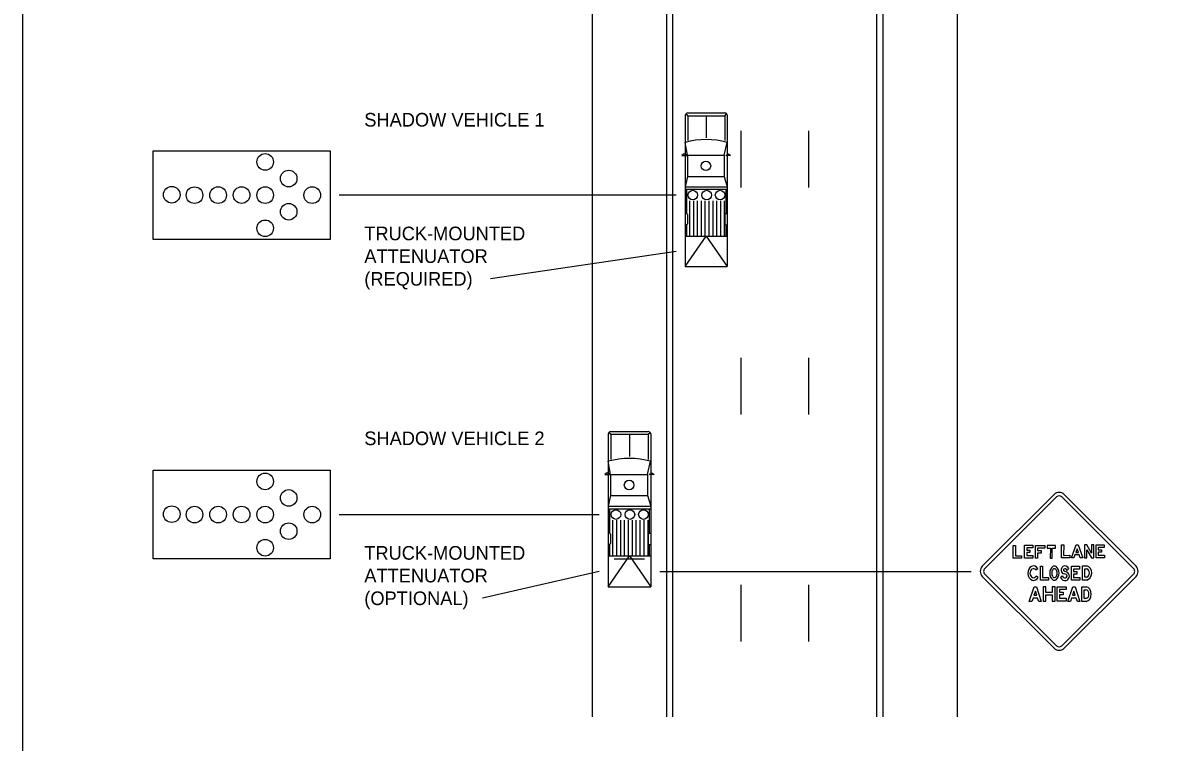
# Model space of a CAD drawing. Extents: x 49991.4 to 50021, y 49987.6 to 50011.4.
# Drawn here: x 49999.38 to 50004.39, y 49992.66 to 49995.83 of the extents above; entities that cross this region are included whole.
import ezdxf

# ---------------------------------------------------------------- set-up
doc = ezdxf.new("R2010")
doc.units = 0
for name, color, linetype in [('Level 1', 7, 'Continuous'), ('Level 2', 7, 'Continuous'), ('Level 3', 7, 'Continuous')]:
    doc.layers.add(name, color=color, linetype=linetype)

msp = doc.modelspace()

# ---------------------------------------------------------------- linework, layer by layer
at = {"layer": 'Level 1'}
for p, q in [((50001.8915, 49992.7699), (50001.8915, 49997.7045)), ((50002.2188, 49992.7699), (50002.2188, 49997.7045)), ((50002.2461, 49992.7699), (50002.2461, 49997.7045)), ((50003.1448, 49992.7699), (50003.1448, 49997.7045)), ((50003.172, 49992.7699), (50003.172, 49997.7045)), ((50003.4993, 49992.7699), (50003.4993, 49997.7045)), ((50002.3118, 49995.431), (50002.475, 49995.431)), ((50002.3002, 49995.4193), (50002.3002, 49994.754)), ((50002.3118, 49995.4189), (50002.3044, 49995.428)), ((50002.3118, 49995.4189), (50002.475, 49995.4189)), ((50002.3118, 49995.4189), (50002.3118, 49995.3096)), ((50002.3934, 49995.4189), (50002.3934, 49995.3217)), ((50002.475, 49995.4189), (50002.4827, 49995.4274)), ((50002.475, 49995.4189), (50002.475, 49995.3096)), ((50002.4854, 49995.4211), (50002.4854, 49994.7541)), ((50002.5461, 49995.1021), (50002.5461, 49995.352)), ((50002.8448, 49995.1021), (50002.8448, 49995.352)), ((50002.3104, 49995.2442), (50002.3001, 49995.3012)), ((50002.4721, 49995.2442), (50002.485, 49995.3012)), ((50002.3104, 49995.2442), (50002.4721, 49995.2442)), ((50002.3104, 49995.2439), (50002.3104, 49995.1518)), ((50002.4721, 49995.2439), (50002.4721, 49995.1518)), ((50002.3104, 49995.1515), (50002.3002, 49995.1052)), ((50002.3104, 49995.1515), (50002.4721, 49995.1515)), ((50002.4721, 49995.1515), (50002.4854, 49995.1052)), ((50002.3002, 49995.1052), (50002.4854, 49995.1052)), ((50002.3002, 49995.0944), (50002.4854, 49995.0944)), ((50002.3054, 49995.0944), (50002.3054, 49994.9873)), ((50002.4791, 49995.0944), (50002.4791, 49994.9873)), ((50002.3193, 49995.0437), (50002.3193, 49994.8882)), ((50002.3363, 49995.0437), (50002.3363, 49994.8882)), ((50002.3533, 49995.0437), (50002.3533, 49994.8882)), ((50002.3704, 49995.0437), (50002.3704, 49994.8882)), ((50002.3874, 49995.0437), (50002.3874, 49994.8882)), ((50002.4044, 49995.0437), (50002.4044, 49994.8882)), ((50002.4214, 49995.0437), (50002.4214, 49994.8882)), ((50002.4384, 49995.0437), (50002.4384, 49994.8882)), ((50002.4554, 49995.0437), (50002.4554, 49994.8882)), ((50002.4724, 49995.0437), (50002.4724, 49994.8882)), ((50002.3066, 49994.9873), (50002.3002, 49994.9873)), ((50002.3108, 49994.9831), (50002.3108, 49994.9425)), ((50002.4748, 49994.9831), (50002.4748, 49994.9425)), ((50002.479, 49994.9873), (50002.4854, 49994.9873)), ((50002.3066, 49994.9383), (50002.3002, 49994.9383)), ((50002.3054, 49994.9383), (50002.3054, 49994.8882)), ((50002.479, 49994.9383), (50002.4854, 49994.9383)), ((50002.4791, 49994.9383), (50002.4791, 49994.8882)), ((50002.3002, 49994.8882), (50002.4854, 49994.8882)), ((50002.3002, 49994.754), (50002.4854, 49994.7541)), ((50002.5461, 49994.1021), (50002.5461, 49994.3521)), ((50002.8448, 49994.1021), (50002.8448, 49994.3521)), ((50001.9613, 49994.0154), (50001.9613, 49993.3434)), ((50001.973, 49994.015), (50001.9656, 49994.0241)), ((50001.973, 49994.0272), (50002.1379, 49994.0272)), ((50001.973, 49994.015), (50002.1379, 49994.015)), ((50001.973, 49994.015), (50001.973, 49993.9045)), ((50002.0555, 49994.015), (50002.0555, 49993.9168)), ((50002.1379, 49994.015), (50002.1456, 49994.0235)), ((50002.1379, 49994.015), (50002.1379, 49993.9045)), ((50002.1484, 49994.0171), (50002.1484, 49993.3434)), ((50001.9716, 49993.8384), (50001.9612, 49993.896)), ((50002.135, 49993.8384), (50002.148, 49993.896)), ((50001.9716, 49993.8384), (50002.135, 49993.8384)), ((50001.9716, 49993.8382), (50001.9716, 49993.7451)), ((50002.135, 49993.8382), (50002.135, 49993.7451)), ((50001.9716, 49993.7449), (50001.9613, 49993.6981)), ((50001.9716, 49993.7449), (50002.135, 49993.7449)), ((50002.135, 49993.7449), (50002.1484, 49993.6981)), ((50003.9244, 49993.7495), (50003.6086, 49993.4337)), ((50003.9351, 49993.7388), (50003.6193, 49993.423)), ((50003.9351, 49993.7388), (50003.6193, 49993.423)), ((50003.6193, 49993.423), (50003.9351, 49993.7388)), ((50004.2747, 49993.423), (50003.9589, 49993.7388)), ((50004.2747, 49993.423), (50003.9589, 49993.7388)), ((50004.2853, 49993.4337), (50003.9695, 49993.7495)), ((50001.9613, 49993.6981), (50002.1484, 49993.6981)), ((50001.9613, 49993.6871), (50002.1484, 49993.6871)), ((50001.9665, 49993.6871), (50001.9665, 49993.579)), ((50002.142, 49993.6871), (50002.142, 49993.579)), ((50001.9806, 49993.6359), (50001.9806, 49993.4788)), ((50001.9978, 49993.6359), (50001.9978, 49993.4788)), ((50002.015, 49993.6359), (50002.015, 49993.4788)), ((50002.0322, 49993.6359), (50002.0322, 49993.4788)), ((50002.0494, 49993.6359), (50002.0494, 49993.4788)), ((50002.0665, 49993.6359), (50002.0665, 49993.4788)), ((50002.0837, 49993.6359), (50002.0837, 49993.4788)), ((50002.1009, 49993.6359), (50002.1009, 49993.4788)), ((50002.1181, 49993.6359), (50002.1181, 49993.4788)), ((50002.1353, 49993.6359), (50002.1353, 49993.4788)), ((50001.9677, 49993.579), (50001.9613, 49993.579)), ((50002.142, 49993.579), (50002.1484, 49993.579)), ((50001.9677, 49993.5294), (50001.9613, 49993.5294)), ((50001.9665, 49993.5294), (50001.9665, 49993.4788)), ((50001.972, 49993.5747), (50001.972, 49993.5337)), ((50002.1377, 49993.5747), (50002.1377, 49993.5337)), ((50002.142, 49993.5294), (50002.1484, 49993.5294)), ((50002.142, 49993.5294), (50002.142, 49993.4788)), ((50003.957, 49993.4705), (50003.957, 49993.5273)), ((50003.957, 49993.5273), (50003.9669, 49993.5273)), ((50003.9669, 49993.5273), (50003.9667, 49993.4815)), ((50004.0008, 49993.4706), (50004.0214, 49993.5274)), ((50004.0214, 49993.5274), (50004.0309, 49993.5274)), ((50004.0309, 49993.5274), (50004.0505, 49993.4706)), ((50004.0686, 49993.5273), (50004.0591, 49993.5273)), ((50004.0591, 49993.5273), (50004.0591, 49993.4703)), ((50004.0893, 49993.4913), (50004.0686, 49993.5273)), ((50004.099, 49993.5273), (50004.0893, 49993.5273)), ((50004.0893, 49993.5273), (50004.0893, 49993.4913)), ((50004.099, 49993.4703), (50004.099, 49993.5273)), ((50004.1096, 49993.4706), (50004.1096, 49993.5276)), ((50004.1096, 49993.5276), (50004.1455, 49993.5276)), ((50004.1455, 49993.5276), (50004.1455, 49993.5162)), ((50001.9613, 49993.4788), (50002.1484, 49993.4789)), ((50003.7451, 49993.4688), (50003.7451, 49993.5256)), ((50003.7451, 49993.5256), (50003.7551, 49993.5256)), ((50003.7551, 49993.5256), (50003.7549, 49993.4798)), ((50003.7549, 49993.4798), (50003.7815, 49993.4801)), ((50003.7815, 49993.4801), (50003.7815, 49993.4688)), ((50003.7944, 49993.4689), (50003.7944, 49993.5259)), ((50003.7944, 49993.5259), (50003.8303, 49993.5259)), ((50003.8303, 49993.5145), (50003.8039, 49993.5145)), ((50003.8039, 49993.5145), (50003.8039, 49993.5048)), ((50003.8039, 49993.5048), (50003.8183, 49993.5048)), ((50003.8183, 49993.4934), (50003.8039, 49993.4934)), ((50003.8039, 49993.4934), (50003.8039, 49993.4804)), ((50003.8039, 49993.4804), (50003.8316, 49993.4804)), ((50003.8183, 49993.5048), (50003.8183, 49993.4934)), ((50003.8303, 49993.5259), (50003.8303, 49993.5145)), ((50003.8316, 49993.4804), (50003.8316, 49993.4689)), ((50003.8426, 49993.4685), (50003.8426, 49993.5246)), ((50003.8426, 49993.5246), (50003.8846, 49993.5246)), ((50003.8846, 49993.5134), (50003.8521, 49993.5134)), ((50003.8521, 49993.5134), (50003.8521, 49993.503)), ((50003.8521, 49993.503), (50003.867, 49993.503)), ((50003.867, 49993.4918), (50003.8521, 49993.4918)), ((50003.8521, 49993.4918), (50003.8521, 49993.4685)), ((50003.867, 49993.503), (50003.867, 49993.4918)), ((50003.8846, 49993.5246), (50003.8846, 49993.5134)), ((50003.9307, 49993.5247), (50003.8944, 49993.5247)), ((50003.8944, 49993.5247), (50003.8944, 49993.5136)), ((50003.8944, 49993.5136), (50003.9081, 49993.5136)), ((50003.9081, 49993.5136), (50003.9079, 49993.4688)), ((50003.9168, 49993.4688), (50003.9168, 49993.5136)), ((50003.9168, 49993.5136), (50003.9307, 49993.5136)), ((50003.9307, 49993.5136), (50003.9307, 49993.5247)), ((50003.9667, 49993.4815), (50003.9933, 49993.4818)), ((50003.9933, 49993.4818), (50003.9933, 49993.4705)), ((50004.0163, 49993.4839), (50004.0115, 49993.4706)), ((50004.0354, 49993.4839), (50004.0163, 49993.4839)), ((50004.0261, 49993.5108), (50004.0203, 49993.4947)), ((50004.0203, 49993.4947), (50004.0316, 49993.4947)), ((50004.0316, 49993.4947), (50004.0261, 49993.5108)), ((50004.04, 49993.4706), (50004.0354, 49993.4839)), ((50004.0686, 49993.4703), (50004.0686, 49993.5063)), ((50004.0686, 49993.5063), (50004.0893, 49993.4703)), ((50004.1455, 49993.5162), (50004.1191, 49993.5162)), ((50004.1191, 49993.5162), (50004.1191, 49993.5065)), ((50004.1191, 49993.5065), (50004.1335, 49993.5065)), ((50004.1335, 49993.4952), (50004.1191, 49993.4952)), ((50004.1191, 49993.4952), (50004.1191, 49993.4821)), ((50004.1191, 49993.4821), (50004.1468, 49993.4821)), ((50004.1335, 49993.5065), (50004.1335, 49993.4952)), ((50004.1468, 49993.4821), (50004.1468, 49993.4706)), ((50001.9875, 49993.4662), (50002.1215, 49993.4662)), ((50003.7815, 49993.4688), (50003.7451, 49993.4688)), ((50003.8316, 49993.4689), (50003.7944, 49993.4689)), ((50003.8521, 49993.4685), (50003.8426, 49993.4685)), ((50003.8644, 49993.372), (50003.8644, 49993.4338)), ((50003.8644, 49993.4338), (50003.8743, 49993.4338)), ((50003.8743, 49993.4338), (50003.8741, 49993.384)), ((50003.9079, 49993.4688), (50003.9168, 49993.4688)), ((50003.9933, 49993.4705), (50003.957, 49993.4705)), ((50004.0115, 49993.4706), (50004.0008, 49993.4706)), ((50004.0013, 49993.3718), (50004.0013, 49993.4337)), ((50004.0013, 49993.4337), (50004.0372, 49993.4337)), ((50004.0372, 49993.4337), (50004.0372, 49993.4214)), ((50004.0507, 49993.4706), (50004.04, 49993.4706)), ((50004.0504, 49993.3729), (50004.0504, 49993.4348)), ((50004.0504, 49993.4348), (50004.0504, 49993.4347)), ((50004.0504, 49993.4347), (50004.0687, 49993.4347)), ((50004.0591, 49993.4703), (50004.0686, 49993.4703)), ((50004.0893, 49993.4703), (50004.099, 49993.4703)), ((50004.1468, 49993.4706), (50004.1096, 49993.4706)), ((50003.6086, 49993.3886), (50003.9244, 49993.0728)), ((50003.6193, 49993.3992), (50003.9351, 49993.0834)), ((50003.6193, 49993.3992), (50003.9351, 49993.0834)), ((50003.8445, 49993.4175), (50003.8535, 49993.4229)), ((50003.8445, 49993.4175), (50003.8445, 49993.4175)), ((50003.8549, 49993.3857), (50003.8459, 49993.3905)), ((50003.8741, 49993.384), (50003.9007, 49993.3842)), ((50003.9007, 49993.3842), (50003.9007, 49993.372)), ((50003.9598, 49993.3909), (50003.9524, 49993.3846)), ((50003.9589, 49993.0834), (50004.2747, 49993.3992)), ((50003.9589, 49993.0834), (50004.2747, 49993.3992)), ((50003.9695, 49993.0728), (50004.2853, 49993.3886)), ((50003.9827, 49993.4155), (50003.9901, 49993.4234)), ((50004.0372, 49993.4214), (50004.0108, 49993.4214)), ((50004.0108, 49993.4214), (50004.0108, 49993.4108)), ((50004.0108, 49993.4108), (50004.0252, 49993.4108)), ((50004.0252, 49993.3984), (50004.0108, 49993.3984)), ((50004.0108, 49993.3984), (50004.0108, 49993.3843)), ((50004.0108, 49993.3843), (50004.0385, 49993.3843)), ((50004.0252, 49993.4108), (50004.0252, 49993.3984)), ((50004.0385, 49993.3843), (50004.0385, 49993.3718)), ((50004.06, 49993.3853), (50004.06, 49993.4224)), ((50004.06, 49993.4224), (50004.0673, 49993.4224)), ((50004.0673, 49993.3853), (50004.06, 49993.3853)), ((50001.9613, 49993.3434), (50002.1484, 49993.3434)), ((50002.5461, 49993.1021), (50002.5461, 49993.3521)), ((50002.8448, 49993.1021), (50002.8448, 49993.3521)), ((50003.8152, 49993.2786), (50003.8371, 49993.3424)), ((50003.8371, 49993.3424), (50003.8473, 49993.3424)), ((50003.8473, 49993.3424), (50003.8682, 49993.2786)), ((50003.9007, 49993.372), (50003.8644, 49993.372)), ((50003.9188, 49993.3738), (50003.9188, 49993.3738)), ((50003.9389, 49993.2793), (50003.9389, 49993.3434)), ((50003.9389, 49993.3434), (50003.9772, 49993.3434)), ((50003.9772, 49993.3306), (50003.9491, 49993.3306)), ((50003.9491, 49993.3306), (50003.9491, 49993.3196)), ((50003.9772, 49993.3434), (50003.9772, 49993.3306)), ((50003.9852, 49993.2786), (50004.0071, 49993.3424)), ((50004.0385, 49993.3718), (50004.0013, 49993.3718)), ((50004.0071, 49993.3424), (50004.0173, 49993.3424)), ((50004.0173, 49993.3424), (50004.0382, 49993.2786)), ((50004.0463, 49993.2788), (50004.0463, 49993.3428)), ((50004.0463, 49993.3428), (50004.0463, 49993.3427)), ((50004.0463, 49993.3427), (50004.0658, 49993.3427)), ((50004.0696, 49993.3729), (50004.0504, 49993.3729)), ((50004.0564, 49993.2916), (50004.0564, 49993.33)), ((50004.0564, 49993.33), (50004.0643, 49993.33)), ((50003.8267, 49993.2786), (50003.8152, 49993.2786)), ((50003.8318, 49993.2935), (50003.8267, 49993.2786)), ((50003.8521, 49993.2935), (50003.8318, 49993.2935)), ((50003.8422, 49993.3238), (50003.836, 49993.3058)), ((50003.836, 49993.3058), (50003.8481, 49993.3058)), ((50003.8481, 49993.3058), (50003.8422, 49993.3238)), ((50003.857, 49993.2786), (50003.8521, 49993.2935)), ((50003.8684, 49993.2786), (50003.857, 49993.2786)), ((50003.9785, 49993.2793), (50003.9389, 49993.2793)), ((50003.9491, 49993.3196), (50003.9644, 49993.3196)), ((50003.9644, 49993.3069), (50003.9491, 49993.3069)), ((50003.9491, 49993.3069), (50003.9491, 49993.2922)), ((50003.9491, 49993.2922), (50003.9785, 49993.2922)), ((50003.9644, 49993.3196), (50003.9644, 49993.3069)), ((50003.9785, 49993.2923), (50003.9785, 49993.2793)), ((50003.9967, 49993.2786), (50003.9852, 49993.2786)), ((50004.0018, 49993.2935), (50003.9967, 49993.2786)), ((50004.0221, 49993.2935), (50004.0018, 49993.2935)), ((50004.0122, 49993.3238), (50004.006, 49993.3058)), ((50004.006, 49993.3058), (50004.0181, 49993.3058)), ((50004.0181, 49993.3058), (50004.0122, 49993.3238)), ((50004.027, 49993.2786), (50004.0221, 49993.2935)), ((50004.0384, 49993.2786), (50004.027, 49993.2786)), ((50004.0666, 49993.2788), (50004.0463, 49993.2788)), ((50004.0643, 49993.2916), (50004.0564, 49993.2916))]:
    msp.add_line(p, q, dxfattribs=at)
for points in [[(49999.3835, 49998.9992), (50016.7501, 49998.9992), (50016.7501, 49987.7988), (49999.3835, 49987.7988)], [(50000.7371, 49994.874), (49999.9574, 49994.874), (49999.9574, 49995.264), (50000.7371, 49995.264)], [(50000.7371, 49994.874), (49999.9574, 49994.874), (49999.9574, 49995.264), (50000.7371, 49995.264)], [(50000.7371, 49993.4665), (49999.9574, 49993.4665), (49999.9574, 49993.8565), (50000.7371, 49993.8565)], [(50000.7371, 49993.4665), (49999.9574, 49993.4665), (49999.9574, 49993.8565), (50000.7371, 49993.8565)], [(50003.8759, 49993.3428), (50003.8759, 49993.28), (50003.8886, 49993.28), (50003.8886, 49993.3071), (50003.9159, 49993.3071), (50003.9159, 49993.28), (50003.9287, 49993.28), (50003.9287, 49993.3428), (50003.9159, 49993.3428), (50003.9159, 49993.3179), (50003.8886, 49993.3182), (50003.8886, 49993.3428)]]:
    msp.add_lwpolyline(points, close=True, dxfattribs=at)
for points in [[(50002.3073, 49995.2434), (50002.2956, 49995.2505), (50002.2859, 49995.2434), (50002.3073, 49995.2434)], [(50002.4789, 49995.2436), (50002.4906, 49995.2507), (50002.5003, 49995.2436), (50002.4789, 49995.2436)], [(50002.3002, 49994.754), (50002.3928, 49994.8882), (50002.4854, 49994.7541)], [(50001.9685, 49993.8377), (50001.9566, 49993.8449), (50001.9469, 49993.8377), (50001.9685, 49993.8377)], [(50002.1418, 49993.8378), (50002.1537, 49993.845), (50002.1635, 49993.8378), (50002.1418, 49993.8378)], [(50001.9613, 49993.3434), (50002.0549, 49993.4789), (50002.1484, 49993.3434)]]:
    msp.add_lwpolyline(points, dxfattribs=at)
for centre, radius in [((50000.451, 49995.215), 0.0366), ((50000.5545, 49995.1419), 0.0366), ((50002.3915, 49995.1977), 0.0211), ((50000.0394, 49995.0706), 0.0366), ((50000.1399, 49995.0686), 0.0366), ((50000.2439, 49995.0688), 0.0366), ((50000.3472, 49995.069), 0.0366), ((50000.451, 49995.0688), 0.0366), ((50000.6581, 49995.0688), 0.0366), ((50002.3337, 49995.069), 0.0211), ((50002.3947, 49995.069), 0.0211), ((50002.454, 49995.069), 0.0211), ((50000.5545, 49994.9957), 0.0366), ((50000.451, 49994.9226), 0.0366), ((50000.451, 49993.8075), 0.0366), ((50002.0535, 49993.7915), 0.0213), ((50000.5545, 49993.7344), 0.0366), ((50000.0394, 49993.6631), 0.0366), ((50000.1399, 49993.6611), 0.0366), ((50000.2439, 49993.6613), 0.0366), ((50000.3472, 49993.6615), 0.0366), ((50000.451, 49993.6613), 0.0366), ((50000.6581, 49993.6613), 0.0366), ((50001.9952, 49993.6615), 0.0213), ((50002.0567, 49993.6615), 0.0213), ((50002.1167, 49993.6615), 0.0213), ((50000.5545, 49993.5882), 0.0366), ((50000.451, 49993.5151), 0.0366)]:
    msp.add_circle(centre, radius, dxfattribs=at)
for centre, radius, start, end in [((50002.3127, 49995.4185), 0.0125, 92.7859, 176.3711), ((50002.4745, 49995.4201), 0.011, 5.1286, 87.8426), ((50002.3926, 49994.9656), 0.3481, 74.595, 105.405), ((50002.3066, 49994.9831), 0.00425, 0, 90), ((50002.479, 49994.9831), 0.00425, 90, 180), ((50002.3066, 49994.9425), 0.00425, 270, 0), ((50002.479, 49994.9425), 0.00425, 180, 270), ((50001.9739, 49994.0146), 0.0127, 92.7859, 176.3711), ((50002.1374, 49994.0161), 0.0111, 5.1286, 87.8426), ((50002.0546, 49993.5571), 0.3516, 74.595, 105.405), ((50003.947, 49993.7269), 0.0319, 45.0001, 134.9999), ((50003.947, 49993.7269), 0.0168, 45.0001, 134.9999), ((50001.9677, 49993.5747), 0.0043, 0, 90), ((50002.142, 49993.5747), 0.0043, 90, 180), ((50001.9677, 49993.5337), 0.0043, 270, 0), ((50002.142, 49993.5337), 0.0043, 180, 270), ((50003.6312, 49993.4111), 0.0319, 134.9999, 225.0001), ((50004.2628, 49993.4111), 0.0319, 314.9999, 45.0001), ((50003.6312, 49993.4111), 0.0168, 134.9999, 225.0001), ((50004.2628, 49993.4111), 0.0168, 314.9999, 45.0001), ((50003.947, 49993.0953), 0.0168, 225.0001, 314.9999), ((50003.947, 49993.0953), 0.0319, 225.0001, 314.9999)]:
    msp.add_arc(centre, radius, start, end, dxfattribs=at)
for centre, major_axis, ratio, start_param, end_param in [((50003.8339, 49993.403), (0, 0.0321), 0.776472, 5.379631, 10.427962), ((50003.9317, 49993.403), (0, 0.0336), 0.776472, 0.534461, 2.621634), ((50003.9263, 49993.4088), (0, 0.0252), 0.776472, 5.919385, 6.698067), ((50003.9205, 49993.4031), (0, 0.0336), 0.776472, 3.656394, 5.769828), ((50003.9691, 49993.4169), (0, 0.0172), 0.776472, 0.444545, 1.431574), ((50003.972, 49993.4051), (0, 0.0296), 0.776472, 5.376315, 6.670748), ((50004.0661, 49993.4038), (0, 0.0311), 0.776472, 3.228698, 6.173105), ((50003.8339, 49993.403), (0, 0.0199), 0.776472, 5.527156, 10.314156), ((50003.9316, 49993.4031), (0, 0.0227), 0.776472, 0.763949, 2.374055), ((50003.9261, 49993.4095), (0, 0.0131), 0.776472, 5.579375, 6.989138), ((50003.9261, 49993.3969), (0, -0.0132), 0.776472, 5.580322, 6.990894), ((50003.9205, 49993.4031), (0, 0.0227), 0.776472, 3.911794, 5.521756), ((50003.9718, 49993.3995), (0, -0.029), 0.776472, 5.252808, 6.528416), ((50003.9687, 49993.4165), (0, -0.0169), 0.776472, 4.545753, 4.838683), ((50003.9703, 49993.42), (0, -0.0196), 0.776472, 5.002827, 5.590799), ((50003.9718, 49993.3995), (0, -0.0177), 0.776472, 5.221087, 6.528416), ((50003.9749, 49993.4353), (0, -0.0355), 0.776472, 5.736507, 6.113108), ((50003.9686, 49993.4174), (0, -0.0042), 0.776472, 3.673328, 5.369364), ((50003.9729, 49993.4247), (0, -0.0132), 0.776472, 5.547951, 6.012148), ((50003.972, 49993.4051), (0, 0.0172), 0.776472, 5.357768, 6.670748), ((50003.9482, 49993.3008), (0, 0.1147), 0.776472, 5.862581, 6.034125), ((50003.9685, 49993.3722), (0, 0.0282), 0.776472, 5.748009, 6.204171), ((50003.9738, 49993.3937), (0, -0.0115), 0.776472, 0.151015, 1.255419), ((50003.9739, 49993.3964), (0, -0.0255), 0.776472, 0.172378, 1.048756), ((50003.9771, 49993.3906), (0, 0.00668), 0.776472, 4.641344, 5.760516), ((50003.9722, 49993.3814), (0, 0.0288), 0.776472, 5.252669, 5.700256), ((50003.9774, 49993.3908), (0, 0.0189), 0.776472, 4.332001, 5.007797), ((50004.0661, 49993.4038), (0, 0.0186), 0.776472, 3.228698, 6.19608), ((50003.926, 49993.3965), (0, -0.0245), 0.776472, 5.893667, 6.677762), ((50004.0629, 49993.3108), (0, 0.0192), 0.8, 3.228698, 6.19608), ((50004.0629, 49993.3108), (0, 0.0321), 0.8, 3.228698, 6.173105)]:
    msp.add_ellipse(centre, major_axis=major_axis, ratio=ratio, start_param=start_param, end_param=end_param, dxfattribs=at)
at = {"layer": 'Level 3'}
for p, q in [((50002.2602, 49995.069), (50000.7771, 49995.069)), ((50002.2602, 49994.8211), (50001.443, 49994.6999)), ((50000.7771, 49993.6615), (50001.9213, 49993.6615)), ((50001.9213, 49993.4111), (50001.4074, 49993.2924)), ((50002.1884, 49993.4111), (50003.5593, 49993.4111))]:
    msp.add_line(p, q, dxfattribs=at)

# ---------------------------------------------------------------- texts
at = {"layer": 'Level 2'}
for s, p in [('SHADOW VEHICLE 1', (50000.8875, 49995.371)), ('TRUCK-MOUNTED', (50000.8875, 49994.8699)), ('ATTENUATOR', (50000.8875, 49994.7699)), ('(REQUIRED)', (50000.8875, 49994.6699)), ('SHADOW VEHICLE 2', (50000.8875, 49993.9672)), ('TRUCK-MOUNTED', (50000.8875, 49993.4624)), ('ATTENUATOR', (50000.8875, 49993.3624)), ('(OPTIONAL)', (50000.8875, 49993.2624))]:
    msp.add_text(s, height=0.06, dxfattribs=at).set_placement(p)

doc.saveas('drawing.dxf')
